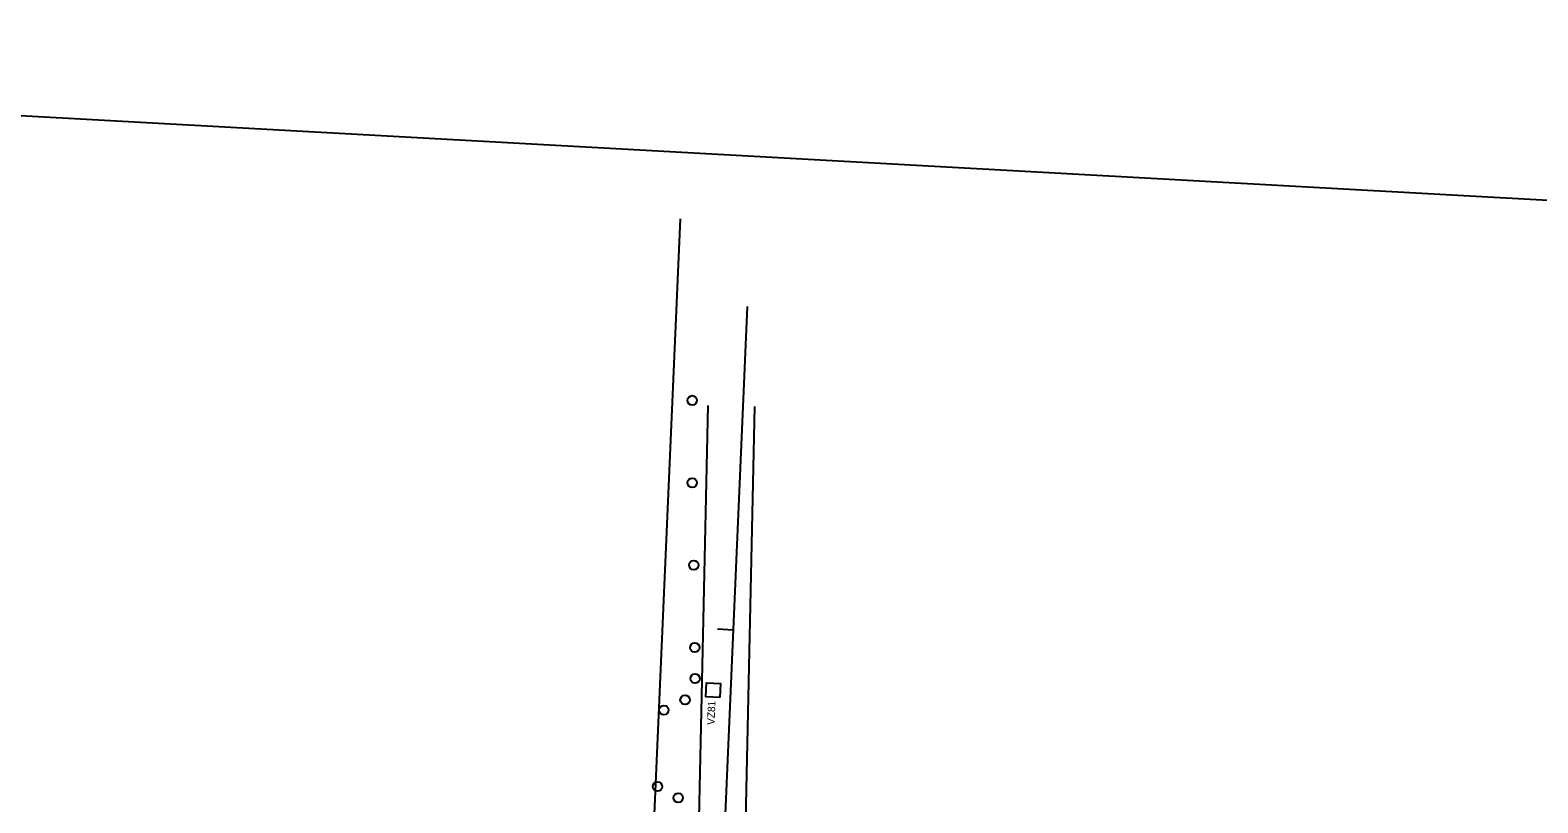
# Model space of a CAD drawing. Extents: x 679444 to 687671, y 733868 to 736107.
# Drawn here: x 683317 to 683958, y 735230 to 735558 of the extents above; entities that cross this region are included whole.
import ezdxf

# ---------------------------------------------------------------- set-up
doc = ezdxf.new("R2010")
doc.units = 0
for name, color, linetype in [('$', 7, 'Continuous'), ('border All Plan 20-40_Border 3 - Level 1', 7, 'Continuous'), ('MOT Stage 1', 7, 'Continuous'), ('MOT Stage 1 Lanes', 7, 'Continuous'), ('R_Horz Alg Station', 7, 'Continuous'), ('RW-EX', 7, 'Continuous'), ('Video-Zones-pr', 7, 'Continuous')]:
    doc.layers.add(name, color=color, linetype=linetype)

# ---------------------------------------------------------------- blocks, each defined once
blk = doc.blocks.new('BAREL_1720')
at = {"layer": 'MOT Stage 1'}
blk.add_circle((0, 0.01), 2.88, dxfattribs=at)
blk = doc.blocks.new('BAREL_1721')
at = {"layer": 'MOT Stage 1'}
blk.add_circle((0, 0.01), 2.88, dxfattribs=at)
blk = doc.blocks.new('BAREL_1722')
at = {"layer": 'MOT Stage 1'}
blk.add_circle((0, 0.01), 2.88, dxfattribs=at)
blk = doc.blocks.new('BAREL_1723')
at = {"layer": 'MOT Stage 1'}
blk.add_circle((0, 0.01), 2.88, dxfattribs=at)
blk = doc.blocks.new('BAREL_1724')
at = {"layer": 'MOT Stage 1'}
blk.add_circle((0, 0.01), 2.88, dxfattribs=at)
blk = doc.blocks.new('BAREL_1725')
at = {"layer": 'MOT Stage 1'}
blk.add_circle((0, 0.01), 2.88, dxfattribs=at)
blk = doc.blocks.new('BAREL_1726')
at = {"layer": 'MOT Stage 1'}
blk.add_circle((0, 0.01), 2.88, dxfattribs=at)
blk = doc.blocks.new('BAREL_1727')
at = {"layer": 'MOT Stage 1'}
blk.add_circle((0, 0.01), 2.88, dxfattribs=at)
blk = doc.blocks.new('BAREL_1728')
at = {"layer": 'MOT Stage 1'}
blk.add_circle((0, 0.01), 2.88, dxfattribs=at)

msp = doc.modelspace()

# ---------------------------------------------------------------- linework, layer by layer
at = {"layer": 'border All Plan 20-40_Border 3 - Level 1'}
msp.add_line((682658.17, 735557.86), (684236.65, 735470.4), dxfattribs=at)
at = {"layer": 'MOT Stage 1 Lanes'}
msp.add_lwpolyline([(683604.91, 735398.45), (683600.74, 735203.61), (683598.98, 735163.25), (683593.24, 735081.04), (683613.19, 735079.65), (683618.95, 735162.12), (683620.73, 735202.96), (683624.91, 735398.02)], dxfattribs=at)
at = {"layer": 'R_Horz Alg Station'}
msp.add_lwpolyline([(683609.11, 735303.51), (683615.77, 735303.21)], dxfattribs=at)
at = {"layer": 'RW-EX'}
for p, q in [((683579.69, 735164.78), (683593.35, 735477.74)), ((683621.76, 735440.48), (683606.39, 735088.43))]:
    msp.add_line(p, q, dxfattribs=at)
at = {"layer": 'Video-Zones-pr'}
msp.add_lwpolyline([(683610.12, 735274.41), (683604.13, 735274.67), (683604.39, 735280.67), (683610.38, 735280.41), (683610.12, 735274.41)], dxfattribs=at)

# ---------------------------------------------------------------- block references
at = {"layer": 'MOT Stage 1', "xscale": 0.6945420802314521, "yscale": 0.6945420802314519, "rotation": 87.04179557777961}
for name, p in [('BAREL_1723', (683598.35, 735400.61)), ('BAREL_1722', (683598.35, 735365.61)), ('BAREL_1721', (683598.99, 735330.62)), ('BAREL_1720', (683599.4, 735295.62)), ('BAREL_1728', (683599.54, 735282.44)), ('BAREL_1726', (683586.29, 735269.03)), ('BAREL_1727', (683595.28, 735273.39)), ('BAREL_1725', (683583.6, 735236.56)), ('BAREL_1724', (683592.41, 735231.83))]:
    msp.add_blockref(name, p, dxfattribs=at)

# ---------------------------------------------------------------- texts
at = {"layer": '$'}
msp.add_text('VZ81', height=3.2, rotation=87.50059, dxfattribs=at).set_placement((683607.79, 735262.7))

doc.saveas('drawing.dxf')
